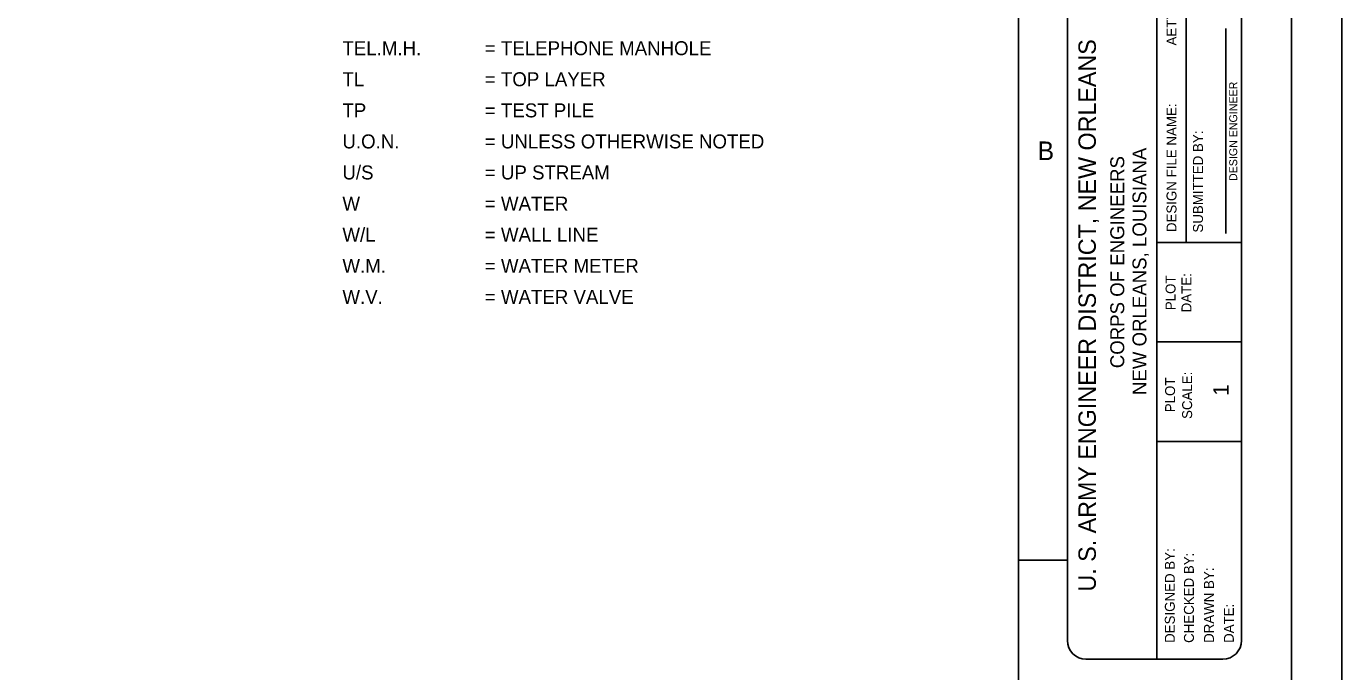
# Model space of a CAD drawing. Extents: x 22369.62 to 22373.29, y 22369.62 to 22372.46.
# Drawn here: x 22372.185 to 22373.288, y 22370.257 to 22370.797 of the extents above; entities that cross this region are included whole.
import ezdxf

# ---------------------------------------------------------------- set-up
doc = ezdxf.new("R2010")
doc.units = 0
for name, color, linetype in [('Level 1', 7, 'Continuous'), ('Level 10', 7, 'Continuous'), ('Level 2', 7, 'Continuous'), ('Level 4', 7, 'Continuous'), ('Level 7', 7, 'Continuous'), ('Level 9', 7, 'Continuous')]:
    doc.layers.add(name, color=color, linetype=linetype)

msp = doc.modelspace()

# ---------------------------------------------------------------- linework, layer by layer
at = {"layer": 'Level 1'}
msp.add_line((22373.133, 22370.9653), (22373.133, 22370.2673), dxfattribs=at)
msp.add_lwpolyline([(22369.6213, 22372.4553), (22373.288, 22372.4553), (22373.288, 22369.6213), (22369.6213, 22369.6213)], close=True, dxfattribs=at)
for points in [[(22373.058, 22370.2829), (22373.058, 22370.9497)], [(22373.204, 22370.2829), (22373.204, 22370.9497)], [(22373.0736, 22370.2673), (22373.1884, 22370.2673)]]:
    msp.add_lwpolyline(points, dxfattribs=at)
for centre, start, end in [((22373.0736, 22370.2829), 180, 270), ((22373.1884, 22370.2829), 270, 0)]:
    msp.add_arc(centre, 0.0156, start, end, dxfattribs=at)
at = {"layer": 'Level 10'}
msp.add_line((22373.017, 22370.3503), (22373.058, 22370.3503), dxfattribs=at)
at = {"layer": 'Level 2'}
for p, q in [((22373.1576, 22370.9653), (22373.1576, 22370.6163)), ((22373.191, 22370.6239), (22373.191, 22370.7956)), ((22373.204, 22370.6163), (22373.133, 22370.6163)), ((22373.204, 22370.533), (22373.133, 22370.533)), ((22373.204, 22370.4496), (22373.133, 22370.4496))]:
    msp.add_line(p, q, dxfattribs=at)
at = {"layer": 'Level 9'}
msp.add_line((22373.246, 22369.6633), (22373.246, 22372.4133), dxfattribs=at)
msp.add_lwpolyline([(22373.017, 22369.6633), (22373.017, 22372.4133)], dxfattribs=at)

# ---------------------------------------------------------------- texts
at = {"layer": 'Level 1'}
for s, height, p in [('AETYP12A.DGN', 0.008333, (22373.1495, 22370.7813)), ('U. S. ARMY ENGINEER DISTRICT, NEW ORLEANS', 0.014583, (22373.0819, 22370.3239)), ('DESIGN ENGINEER', 0.006666, (22373.2004, 22370.6678)), ('DESIGN FILE NAME:', 0.008334, (22373.1495, 22370.625)), ('SUBMITTED BY:', 0.008334, (22373.1717, 22370.6246)), ('PLOT', 0.00833, (22373.1487, 22370.5596)), ('DATE:', 0.00833, (22373.162, 22370.5578)), ('PLOT', 0.00833, (22373.1483, 22370.4741)), ('SCALE:', 0.00833, (22373.1626, 22370.4685)), ('DESIGNED BY:', 0.008334, (22373.1481, 22370.2809)), ('CHECKED BY:', 0.008334, (22373.1641, 22370.2809)), ('DRAWN BY:', 0.00833, (22373.1809, 22370.2809)), ('DATE:', 0.00833, (22373.1976, 22370.2809))]:
    msp.add_text(s, height=height, rotation=90, dxfattribs=at).set_placement(p)
msp.add_text('B', height=0.0156, dxfattribs=at).set_placement((22373.033, 22370.6853))
at = {"layer": 'Level 4'}
for s, height, p in [('TEL.M.H. ', 0.0117, (22372.4503, 22370.7732)), ('= TELEPHONE MANHOLE', 0.011698, (22372.5697, 22370.7732)), ('TL', 0.0117, (22372.4503, 22370.7472)), ('= TOP LAYER', 0.011698, (22372.5697, 22370.7472)), ('TP', 0.0117, (22372.4503, 22370.7211)), ('= TEST PILE', 0.011698, (22372.5697, 22370.7211)), ('U.O.N.', 0.0117, (22372.4503, 22370.6951)), ('= UNLESS OTHERWISE NOTED', 0.011698, (22372.5697, 22370.6951)), ('U/S', 0.0117, (22372.4503, 22370.6691)), ('= UP STREAM', 0.011698, (22372.5697, 22370.6691)), ('W ', 0.0117, (22372.4503, 22370.643)), ('= WATER', 0.0117, (22372.5697, 22370.643)), ('W/L', 0.0117, (22372.4503, 22370.617)), ('= WALL LINE', 0.011698, (22372.5697, 22370.617)), ('W.M.', 0.0117, (22372.4503, 22370.5909)), ('= WATER METER', 0.011698, (22372.5697, 22370.5909)), ('W.V.', 0.0117, (22372.4503, 22370.5649)), ('= WATER VALVE', 0.011698, (22372.5697, 22370.5649))]:
    msp.add_text(s, height=height, dxfattribs=at).set_placement(p)
at = {"layer": 'Level 7'}
for s, height, p in [('NEW ORLEANS, LOUISIANA', 0.011667, (22373.1243, 22370.4885)), ('CORPS OF ENGINEERS', 0.011667, (22373.1057, 22370.511)), ('1', 0.013, (22373.1933, 22370.4879))]:
    msp.add_text(s, height=height, rotation=90, dxfattribs=at).set_placement(p)

doc.saveas('drawing.dxf')
